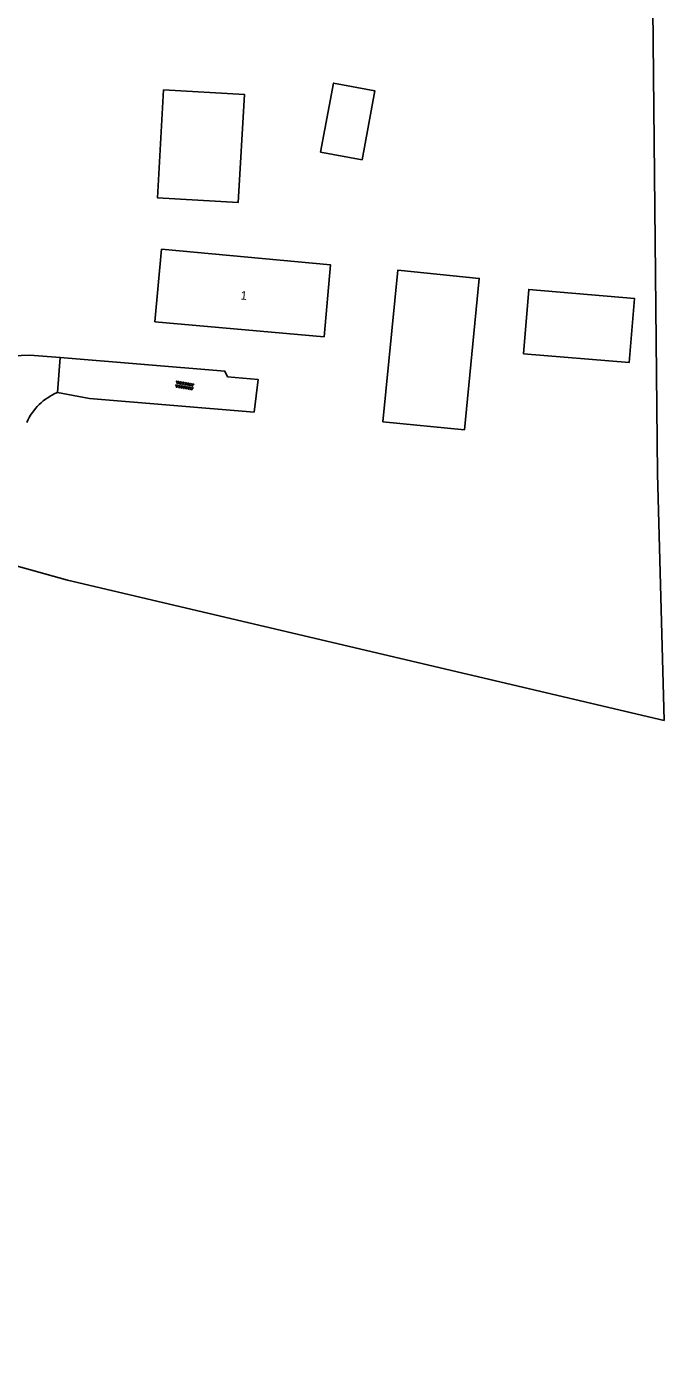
# Model space of a CAD drawing. Extents: x 134297 to 137000, y 403500 to 406000.
# Drawn here: x 135523 to 135597.7, y 404482.3 to 404638.8 of the extents above; entities that cross this region are included whole.
import ezdxf

# ---------------------------------------------------------------- set-up
doc = ezdxf.new("R2010")
doc.units = 0
for name, color, linetype in [('gg-afsc-draadraster', 7, 'Continuous'), ('gg-afsc-lijn draadraster', 7, 'Continuous'), ('gg-anno-huisnummerreeks BGT', 7, 'Continuous'), ('gg-bbg-bijgebouw', 7, 'Continuous'), ('gg-bbg-gedigitaliseerde bebouwing', 7, 'Continuous'), ('gg-bbg-gedigitaliseerde bijgebouw', 7, 'Continuous'), ('gg-bbg-hoofdgebouw', 7, 'Continuous'), ('gg-bbg-open loods', 7, 'Continuous'), ('gg-knt-onverhard', 7, 'Continuous'), ('gg-knt-verharding', 7, 'Continuous'), ('gt-grn-vlakafsluiter', 7, 'Continuous'), ('gt-symb-overige verharding', 7, 'Continuous')]:
    doc.layers.add(name, color=color, linetype=linetype)

# ---------------------------------------------------------------- blocks, each defined once
blk = doc.blocks.new('gt0-OVH')
at = {"layer": 'gt-symb-overige verharding'}
for points in [[(-0.97, 0.3), (-0.97, 0.31), (-0.96, 0.32), (-0.97, 0.33), (-0.97, 0.34), (-0.98, 0.35), (-0.99, 0.35), (-1, 0.36), (-1.01, 0.35), (-1.02, 0.35), (-1.03, 0.34), (-1.03, 0.33), (-1.04, 0.32), (-1.03, 0.31), (-1.03, 0.3), (-1.02, 0.29), (-1.01, 0.29), (-1, 0.28), (-0.99, 0.29), (-0.98, 0.29)], [(-0.87, 0.11), (-0.87, 0.12), (-0.86, 0.13), (-0.87, 0.14), (-0.87, 0.15), (-0.88, 0.16), (-0.89, 0.16), (-0.9, 0.16), (-0.91, 0.16), (-0.92, 0.16), (-0.93, 0.15), (-0.93, 0.14), (-0.94, 0.13), (-0.93, 0.12), (-0.93, 0.11), (-0.92, 0.1), (-0.91, 0.09), (-0.9, 0.09), (-0.89, 0.09), (-0.88, 0.1)], [(-0.77, 0.3), (-0.77, 0.31), (-0.76, 0.32), (-0.77, 0.33), (-0.77, 0.34), (-0.78, 0.35), (-0.79, 0.35), (-0.8, 0.36), (-0.81, 0.35), (-0.82, 0.35), (-0.83, 0.34), (-0.83, 0.33), (-0.84, 0.32), (-0.83, 0.31), (-0.83, 0.3), (-0.82, 0.29), (-0.81, 0.29), (-0.8, 0.28), (-0.79, 0.29), (-0.78, 0.29)], [(-0.67, 0.11), (-0.67, 0.12), (-0.66, 0.13), (-0.67, 0.14), (-0.67, 0.15), (-0.68, 0.16), (-0.69, 0.16), (-0.7, 0.16), (-0.71, 0.16), (-0.72, 0.16), (-0.73, 0.15), (-0.73, 0.14), (-0.74, 0.13), (-0.73, 0.12), (-0.73, 0.11), (-0.72, 0.1), (-0.71, 0.09), (-0.7, 0.09), (-0.69, 0.09), (-0.68, 0.1)], [(-0.57, 0.3), (-0.57, 0.31), (-0.56, 0.32), (-0.57, 0.33), (-0.57, 0.34), (-0.58, 0.35), (-0.59, 0.35), (-0.6, 0.36), (-0.61, 0.35), (-0.62, 0.35), (-0.63, 0.34), (-0.63, 0.33), (-0.64, 0.32), (-0.63, 0.31), (-0.63, 0.3), (-0.62, 0.29), (-0.61, 0.29), (-0.6, 0.28), (-0.59, 0.29), (-0.58, 0.29)], [(-0.47, 0.11), (-0.47, 0.12), (-0.46, 0.13), (-0.47, 0.14), (-0.47, 0.15), (-0.48, 0.16), (-0.49, 0.16), (-0.5, 0.16), (-0.51, 0.16), (-0.52, 0.16), (-0.53, 0.15), (-0.53, 0.14), (-0.54, 0.13), (-0.53, 0.12), (-0.53, 0.11), (-0.52, 0.1), (-0.51, 0.09), (-0.5, 0.09), (-0.49, 0.09), (-0.48, 0.1)], [(-0.37, 0.3), (-0.37, 0.31), (-0.36, 0.32), (-0.37, 0.33), (-0.37, 0.34), (-0.38, 0.35), (-0.39, 0.35), (-0.4, 0.36), (-0.41, 0.35), (-0.42, 0.35), (-0.43, 0.34), (-0.43, 0.33), (-0.44, 0.32), (-0.43, 0.31), (-0.43, 0.3), (-0.42, 0.29), (-0.41, 0.29), (-0.4, 0.28), (-0.39, 0.29), (-0.38, 0.29)], [(-0.27, 0.11), (-0.27, 0.12), (-0.26, 0.13), (-0.27, 0.14), (-0.27, 0.15), (-0.28, 0.16), (-0.29, 0.16), (-0.3, 0.16), (-0.31, 0.16), (-0.32, 0.16), (-0.33, 0.15), (-0.33, 0.14), (-0.34, 0.13), (-0.33, 0.12), (-0.33, 0.11), (-0.32, 0.1), (-0.31, 0.09), (-0.3, 0.09), (-0.29, 0.09), (-0.28, 0.1)], [(-0.17, 0.3), (-0.17, 0.31), (-0.16, 0.32), (-0.17, 0.33), (-0.17, 0.34), (-0.18, 0.35), (-0.19, 0.35), (-0.2, 0.36), (-0.21, 0.35), (-0.22, 0.35), (-0.23, 0.34), (-0.23, 0.33), (-0.24, 0.32), (-0.23, 0.31), (-0.23, 0.3), (-0.22, 0.29), (-0.21, 0.29), (-0.2, 0.28), (-0.19, 0.29), (-0.18, 0.29)], [(-0.07, 0.11), (-0.07, 0.12), (-0.06, 0.13), (-0.07, 0.14), (-0.07, 0.15), (-0.08, 0.16), (-0.09, 0.16), (-0.1, 0.16), (-0.11, 0.16), (-0.12, 0.16), (-0.13, 0.15), (-0.13, 0.14), (-0.14, 0.13), (-0.13, 0.12), (-0.13, 0.11), (-0.12, 0.1), (-0.11, 0.09), (-0.1, 0.09), (-0.09, 0.09), (-0.08, 0.1)], [(0.03, 0.3), (0.03, 0.31), (0.04, 0.32), (0.03, 0.33), (0.03, 0.34), (0.02, 0.35), (0.01, 0.35), (0, 0.36), (-0.01, 0.35), (-0.02, 0.35), (-0.03, 0.34), (-0.03, 0.33), (-0.04, 0.32), (-0.03, 0.31), (-0.03, 0.3), (-0.02, 0.29), (-0.01, 0.29), (0, 0.28), (0.01, 0.29), (0.02, 0.29)], [(0.13, 0.11), (0.13, 0.12), (0.14, 0.13), (0.13, 0.14), (0.13, 0.15), (0.12, 0.16), (0.11, 0.16), (0.1, 0.16), (0.09, 0.16), (0.08, 0.16), (0.07, 0.15), (0.07, 0.14), (0.06, 0.13), (0.07, 0.12), (0.07, 0.11), (0.08, 0.1), (0.09, 0.09), (0.1, 0.09), (0.11, 0.09), (0.12, 0.1)], [(0.23, 0.3), (0.23, 0.31), (0.24, 0.32), (0.23, 0.33), (0.23, 0.34), (0.22, 0.35), (0.21, 0.35), (0.2, 0.36), (0.19, 0.35), (0.18, 0.35), (0.17, 0.34), (0.17, 0.33), (0.16, 0.32), (0.17, 0.31), (0.17, 0.3), (0.18, 0.29), (0.19, 0.29), (0.2, 0.28), (0.21, 0.29), (0.22, 0.29)], [(0.33, 0.11), (0.33, 0.12), (0.34, 0.13), (0.33, 0.14), (0.33, 0.15), (0.32, 0.16), (0.31, 0.16), (0.3, 0.16), (0.29, 0.16), (0.28, 0.16), (0.27, 0.15), (0.27, 0.14), (0.26, 0.13), (0.27, 0.12), (0.27, 0.11), (0.28, 0.1), (0.29, 0.09), (0.3, 0.09), (0.31, 0.09), (0.32, 0.1)], [(0.43, 0.3), (0.43, 0.31), (0.44, 0.32), (0.43, 0.33), (0.43, 0.34), (0.42, 0.35), (0.41, 0.35), (0.4, 0.36), (0.39, 0.35), (0.38, 0.35), (0.37, 0.34), (0.37, 0.33), (0.36, 0.32), (0.37, 0.31), (0.37, 0.3), (0.38, 0.29), (0.39, 0.29), (0.4, 0.28), (0.41, 0.29), (0.42, 0.29)], [(0.53, 0.11), (0.53, 0.12), (0.54, 0.13), (0.53, 0.14), (0.53, 0.15), (0.52, 0.16), (0.51, 0.16), (0.5, 0.16), (0.49, 0.16), (0.48, 0.16), (0.47, 0.15), (0.47, 0.14), (0.46, 0.13), (0.47, 0.12), (0.47, 0.11), (0.48, 0.1), (0.49, 0.09), (0.5, 0.09), (0.51, 0.09), (0.52, 0.1)], [(0.63, 0.3), (0.63, 0.31), (0.64, 0.32), (0.63, 0.33), (0.63, 0.34), (0.62, 0.35), (0.61, 0.35), (0.6, 0.36), (0.59, 0.35), (0.58, 0.35), (0.57, 0.34), (0.57, 0.33), (0.56, 0.32), (0.57, 0.31), (0.57, 0.3), (0.58, 0.29), (0.59, 0.29), (0.6, 0.28), (0.61, 0.29), (0.62, 0.29)], [(0.73, 0.11), (0.73, 0.12), (0.74, 0.13), (0.73, 0.14), (0.73, 0.15), (0.72, 0.16), (0.71, 0.16), (0.7, 0.16), (0.69, 0.16), (0.68, 0.16), (0.67, 0.15), (0.67, 0.14), (0.66, 0.13), (0.67, 0.12), (0.67, 0.11), (0.68, 0.1), (0.69, 0.09), (0.7, 0.09), (0.71, 0.09), (0.72, 0.1)], [(0.83, 0.3), (0.83, 0.31), (0.84, 0.32), (0.83, 0.33), (0.83, 0.34), (0.82, 0.35), (0.81, 0.35), (0.8, 0.36), (0.79, 0.35), (0.78, 0.35), (0.77, 0.34), (0.77, 0.33), (0.76, 0.32), (0.77, 0.31), (0.77, 0.3), (0.78, 0.29), (0.79, 0.29), (0.8, 0.28), (0.81, 0.29), (0.82, 0.29)], [(0.93, 0.11), (0.93, 0.12), (0.94, 0.13), (0.93, 0.14), (0.93, 0.15), (0.92, 0.16), (0.91, 0.16), (0.9, 0.16), (0.89, 0.16), (0.88, 0.16), (0.87, 0.15), (0.87, 0.14), (0.86, 0.13), (0.87, 0.12), (0.87, 0.11), (0.88, 0.1), (0.89, 0.09), (0.9, 0.09), (0.91, 0.09), (0.92, 0.1)], [(1.03, 0.3), (1.03, 0.31), (1.04, 0.32), (1.03, 0.33), (1.03, 0.34), (1.02, 0.35), (1.01, 0.35), (1, 0.36), (0.99, 0.35), (0.98, 0.35), (0.97, 0.34), (0.97, 0.33), (0.96, 0.32), (0.97, 0.31), (0.97, 0.3), (0.98, 0.29), (0.99, 0.29), (1, 0.28), (1.01, 0.29), (1.02, 0.29)], [(-0.97, -0.14), (-0.97, -0.13), (-0.96, -0.12), (-0.97, -0.11), (-0.97, -0.1), (-0.98, -0.09), (-0.99, -0.09), (-1, -0.08), (-1.01, -0.09), (-1.02, -0.09), (-1.03, -0.1), (-1.03, -0.11), (-1.04, -0.12), (-1.03, -0.13), (-1.03, -0.14), (-1.02, -0.15), (-1.01, -0.15), (-1, -0.16), (-0.99, -0.15), (-0.98, -0.15)], [(-0.87, -0.33), (-0.87, -0.32), (-0.86, -0.31), (-0.87, -0.3), (-0.87, -0.29), (-0.88, -0.28), (-0.89, -0.28), (-0.9, -0.28), (-0.91, -0.28), (-0.92, -0.28), (-0.93, -0.29), (-0.93, -0.3), (-0.94, -0.31), (-0.93, -0.32), (-0.93, -0.33), (-0.92, -0.34), (-0.91, -0.35), (-0.9, -0.35), (-0.89, -0.35), (-0.88, -0.34)], [(-0.77, -0.14), (-0.77, -0.13), (-0.76, -0.12), (-0.77, -0.11), (-0.77, -0.1), (-0.78, -0.09), (-0.79, -0.09), (-0.8, -0.08), (-0.81, -0.09), (-0.82, -0.09), (-0.83, -0.1), (-0.83, -0.11), (-0.84, -0.12), (-0.83, -0.13), (-0.83, -0.14), (-0.82, -0.15), (-0.81, -0.15), (-0.8, -0.16), (-0.79, -0.15), (-0.78, -0.15)], [(-0.67, -0.33), (-0.67, -0.32), (-0.66, -0.31), (-0.67, -0.3), (-0.67, -0.29), (-0.68, -0.28), (-0.69, -0.28), (-0.7, -0.28), (-0.71, -0.28), (-0.72, -0.28), (-0.73, -0.29), (-0.73, -0.3), (-0.74, -0.31), (-0.73, -0.32), (-0.73, -0.33), (-0.72, -0.34), (-0.71, -0.35), (-0.7, -0.35), (-0.69, -0.35), (-0.68, -0.34)], [(-0.57, -0.14), (-0.57, -0.13), (-0.56, -0.12), (-0.57, -0.11), (-0.57, -0.1), (-0.58, -0.09), (-0.59, -0.09), (-0.6, -0.08), (-0.61, -0.09), (-0.62, -0.09), (-0.63, -0.1), (-0.63, -0.11), (-0.64, -0.12), (-0.63, -0.13), (-0.63, -0.14), (-0.62, -0.15), (-0.61, -0.15), (-0.6, -0.16), (-0.59, -0.15), (-0.58, -0.15)], [(-0.47, -0.33), (-0.47, -0.32), (-0.46, -0.31), (-0.47, -0.3), (-0.47, -0.29), (-0.48, -0.28), (-0.49, -0.28), (-0.5, -0.28), (-0.51, -0.28), (-0.52, -0.28), (-0.53, -0.29), (-0.53, -0.3), (-0.54, -0.31), (-0.53, -0.32), (-0.53, -0.33), (-0.52, -0.34), (-0.51, -0.35), (-0.5, -0.35), (-0.49, -0.35), (-0.48, -0.34)], [(-0.37, -0.14), (-0.37, -0.13), (-0.36, -0.12), (-0.37, -0.11), (-0.37, -0.1), (-0.38, -0.09), (-0.39, -0.09), (-0.4, -0.08), (-0.41, -0.09), (-0.42, -0.09), (-0.43, -0.1), (-0.43, -0.11), (-0.44, -0.12), (-0.43, -0.13), (-0.43, -0.14), (-0.42, -0.15), (-0.41, -0.15), (-0.4, -0.16), (-0.39, -0.15), (-0.38, -0.15)], [(-0.27, -0.33), (-0.27, -0.32), (-0.26, -0.31), (-0.27, -0.3), (-0.27, -0.29), (-0.28, -0.28), (-0.29, -0.28), (-0.3, -0.28), (-0.31, -0.28), (-0.32, -0.28), (-0.33, -0.29), (-0.33, -0.3), (-0.34, -0.31), (-0.33, -0.32), (-0.33, -0.33), (-0.32, -0.34), (-0.31, -0.35), (-0.3, -0.35), (-0.29, -0.35), (-0.28, -0.34)], [(-0.17, -0.14), (-0.17, -0.13), (-0.16, -0.12), (-0.17, -0.11), (-0.17, -0.1), (-0.18, -0.09), (-0.19, -0.09), (-0.2, -0.08), (-0.21, -0.09), (-0.22, -0.09), (-0.23, -0.1), (-0.23, -0.11), (-0.24, -0.12), (-0.23, -0.13), (-0.23, -0.14), (-0.22, -0.15), (-0.21, -0.15), (-0.2, -0.16), (-0.19, -0.15), (-0.18, -0.15)], [(-0.07, -0.33), (-0.07, -0.32), (-0.06, -0.31), (-0.07, -0.3), (-0.07, -0.29), (-0.08, -0.28), (-0.09, -0.28), (-0.1, -0.28), (-0.11, -0.28), (-0.12, -0.28), (-0.13, -0.29), (-0.13, -0.3), (-0.14, -0.31), (-0.13, -0.32), (-0.13, -0.33), (-0.12, -0.34), (-0.11, -0.35), (-0.1, -0.35), (-0.09, -0.35), (-0.08, -0.34)], [(0.03, -0.14), (0.03, -0.13), (0.04, -0.12), (0.03, -0.11), (0.03, -0.1), (0.02, -0.09), (0.01, -0.09), (0, -0.08), (-0.01, -0.09), (-0.02, -0.09), (-0.03, -0.1), (-0.03, -0.11), (-0.04, -0.12), (-0.03, -0.13), (-0.03, -0.14), (-0.02, -0.15), (-0.01, -0.15), (0, -0.16), (0.01, -0.15), (0.02, -0.15)], [(0.13, -0.33), (0.13, -0.32), (0.14, -0.31), (0.13, -0.3), (0.13, -0.29), (0.12, -0.28), (0.11, -0.28), (0.1, -0.28), (0.09, -0.28), (0.08, -0.28), (0.07, -0.29), (0.07, -0.3), (0.06, -0.31), (0.07, -0.32), (0.07, -0.33), (0.08, -0.34), (0.09, -0.35), (0.1, -0.35), (0.11, -0.35), (0.12, -0.34)], [(0.23, -0.14), (0.23, -0.13), (0.24, -0.12), (0.23, -0.11), (0.23, -0.1), (0.22, -0.09), (0.21, -0.09), (0.2, -0.08), (0.19, -0.09), (0.18, -0.09), (0.17, -0.1), (0.17, -0.11), (0.16, -0.12), (0.17, -0.13), (0.17, -0.14), (0.18, -0.15), (0.19, -0.15), (0.2, -0.16), (0.21, -0.15), (0.22, -0.15)], [(0.33, -0.33), (0.33, -0.32), (0.34, -0.31), (0.33, -0.3), (0.33, -0.29), (0.32, -0.28), (0.31, -0.28), (0.3, -0.28), (0.29, -0.28), (0.28, -0.28), (0.27, -0.29), (0.27, -0.3), (0.26, -0.31), (0.27, -0.32), (0.27, -0.33), (0.28, -0.34), (0.29, -0.35), (0.3, -0.35), (0.31, -0.35), (0.32, -0.34)], [(0.43, -0.14), (0.43, -0.13), (0.44, -0.12), (0.43, -0.11), (0.43, -0.1), (0.42, -0.09), (0.41, -0.09), (0.4, -0.08), (0.39, -0.09), (0.38, -0.09), (0.37, -0.1), (0.37, -0.11), (0.36, -0.12), (0.37, -0.13), (0.37, -0.14), (0.38, -0.15), (0.39, -0.15), (0.4, -0.16), (0.41, -0.15), (0.42, -0.15)], [(0.53, -0.33), (0.53, -0.32), (0.54, -0.31), (0.53, -0.3), (0.53, -0.29), (0.52, -0.28), (0.51, -0.28), (0.5, -0.28), (0.49, -0.28), (0.48, -0.28), (0.47, -0.29), (0.47, -0.3), (0.46, -0.31), (0.47, -0.32), (0.47, -0.33), (0.48, -0.34), (0.49, -0.35), (0.5, -0.35), (0.51, -0.35), (0.52, -0.34)], [(0.63, -0.14), (0.63, -0.13), (0.64, -0.12), (0.63, -0.11), (0.63, -0.1), (0.62, -0.09), (0.61, -0.09), (0.6, -0.08), (0.59, -0.09), (0.58, -0.09), (0.57, -0.1), (0.57, -0.11), (0.56, -0.12), (0.57, -0.13), (0.57, -0.14), (0.58, -0.15), (0.59, -0.15), (0.6, -0.16), (0.61, -0.15), (0.62, -0.15)], [(0.73, -0.33), (0.73, -0.32), (0.74, -0.31), (0.73, -0.3), (0.73, -0.29), (0.72, -0.28), (0.71, -0.28), (0.7, -0.28), (0.69, -0.28), (0.68, -0.28), (0.67, -0.29), (0.67, -0.3), (0.66, -0.31), (0.67, -0.32), (0.67, -0.33), (0.68, -0.34), (0.69, -0.35), (0.7, -0.35), (0.71, -0.35), (0.72, -0.34)], [(0.83, -0.14), (0.83, -0.13), (0.84, -0.12), (0.83, -0.11), (0.83, -0.1), (0.82, -0.09), (0.81, -0.09), (0.8, -0.08), (0.79, -0.09), (0.78, -0.09), (0.77, -0.1), (0.77, -0.11), (0.76, -0.12), (0.77, -0.13), (0.77, -0.14), (0.78, -0.15), (0.79, -0.15), (0.8, -0.16), (0.81, -0.15), (0.82, -0.15)], [(0.93, -0.33), (0.93, -0.32), (0.94, -0.31), (0.93, -0.3), (0.93, -0.29), (0.92, -0.28), (0.91, -0.28), (0.9, -0.28), (0.89, -0.28), (0.88, -0.28), (0.87, -0.29), (0.87, -0.3), (0.86, -0.31), (0.87, -0.32), (0.87, -0.33), (0.88, -0.34), (0.89, -0.35), (0.9, -0.35), (0.91, -0.35), (0.92, -0.34)], [(1.03, -0.14), (1.03, -0.13), (1.04, -0.12), (1.03, -0.11), (1.03, -0.1), (1.02, -0.09), (1.01, -0.09), (1, -0.08), (0.99, -0.09), (0.98, -0.09), (0.97, -0.1), (0.97, -0.11), (0.96, -0.12), (0.97, -0.13), (0.97, -0.14), (0.98, -0.15), (0.99, -0.15), (1, -0.16), (1.01, -0.15), (1.02, -0.15)]]:
    blk.add_lwpolyline(points, close=True, dxfattribs=at)

msp = doc.modelspace()

# ---------------------------------------------------------------- linework, layer by layer
at = {"layer": 'gg-afsc-draadraster'}
for points in [[(135597.73, 404557.48), (135596.95, 404586.38), (135596.25, 404656.52)], [(135463.38, 404419.49), (135462.67, 404420.47), (135463.32, 404425.22), (135464.79, 404432.11), (135470.14, 404446.89), (135481.76, 404478.65), (135489.89, 404500.46), (135505.71, 404543.44), (135516.19, 404571.92), (135518.38, 404576.53), (135527.81, 404573.94), (135597.73, 404557.48)]]:
    msp.add_lwpolyline(points, dxfattribs=at)
at = {"layer": 'gg-afsc-lijn draadraster'}
for points in [[(135597.73, 404557.48), (135596.95, 404586.38), (135596.25, 404656.52)], [(135463.38, 404419.49), (135462.67, 404420.47), (135463.32, 404425.22), (135464.79, 404432.11), (135470.14, 404446.89), (135481.76, 404478.65), (135489.89, 404500.46), (135505.71, 404543.44), (135516.19, 404571.92), (135518.38, 404576.53), (135527.81, 404573.94), (135597.73, 404557.48)]]:
    msp.add_lwpolyline(points, dxfattribs=at)
at = {"layer": 'gg-bbg-bijgebouw'}
msp.add_line((135564.76, 404592.46), (135574.32, 404591.53), dxfattribs=at)
at = {"layer": 'gg-bbg-gedigitaliseerde bebouwing'}
msp.add_lwpolyline([(135538.83, 404612.71), (135558.64, 404610.85), (135557.89, 404602.41)], dxfattribs=at)
at = {"layer": 'gg-bbg-gedigitaliseerde bijgebouw'}
for points in [[(135557.47, 404624.07), (135562.32, 404623.16), (135563.82, 404631.24), (135558.98, 404632.14), (135557.47, 404624.07)], [(135539.05, 404631.36), (135548.53, 404630.82), (135547.82, 404618.18), (135538.34, 404618.72), (135539.05, 404631.36)], [(135574.32, 404591.53), (135576.06, 404609.27), (135566.51, 404610.22), (135564.76, 404592.46)]]:
    msp.add_lwpolyline(points, dxfattribs=at)
at = {"layer": 'gg-bbg-hoofdgebouw'}
for p, q in [((135538.05, 404604.19), (135538.83, 404612.71)), ((135557.89, 404602.41), (135538.05, 404604.19))]:
    msp.add_line(p, q, dxfattribs=at)
at = {"layer": 'gg-bbg-open loods'}
msp.add_lwpolyline([(135581.22, 404600.45), (135593.61, 404599.41), (135594.24, 404606.93), (135581.86, 404607.98), (135581.22, 404600.45)], dxfattribs=at)
at = {"layer": 'gg-knt-onverhard'}
for points in [[(135526.95, 404599.99), (135546.26, 404598.39), (135546.57, 404597.74), (135550.15, 404597.42)], [(135549.68, 404593.59), (135530.4, 404595.22), (135526.64, 404595.9)]]:
    msp.add_lwpolyline(points, dxfattribs=at)
at = {"layer": 'gg-knt-verharding'}
msp.add_line((135526.95, 404599.99), (135526.64, 404595.9), dxfattribs=at)
msp.add_lwpolyline([(135519.35, 404600.13), (135523.38, 404600.26), (135526.95, 404599.99)], dxfattribs=at)
msp.add_arc((135529.29, 404589.58), 6.86, 112.7569, 155.9426, dxfattribs=at)
at = {"layer": 'gt-grn-vlakafsluiter'}
msp.add_line((135550.15, 404597.42), (135549.68, 404593.59), dxfattribs=at)

# ---------------------------------------------------------------- block references
at = {"layer": 'gt-symb-overige verharding', "rotation": -9.500010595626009}
msp.add_blockref('gt0-OVH', (135541.53, 404596.72), dxfattribs=at)

# ---------------------------------------------------------------- texts
at = {"layer": 'gg-anno-huisnummerreeks BGT'}
msp.add_text('1', height=1, rotation=354.9, dxfattribs=at).set_placement((135548.06, 404606.81))

doc.saveas('drawing.dxf')
